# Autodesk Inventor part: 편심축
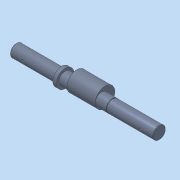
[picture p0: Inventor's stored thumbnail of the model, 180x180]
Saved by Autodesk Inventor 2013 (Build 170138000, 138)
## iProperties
Manager: 한국ATC센터
Company: 한국ATC센터
Created: 2014-10
Part Number: 편심축
Document SubType Name: Modeling
Designer: 한국ATC센터
Density: 7.86 g/cm^3
Material: 강철, 연강
Mass: 1420.77 g
Surface Area: 286.549 cm^2
Volume: 180.76 cm^3
Author: KYOUNG IL JANG
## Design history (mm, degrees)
sketch "스케치1"
  geometry: L1 (-142, 0)-(142, 0); L2 (-142, 0)-(-142, 12.5); L3 (-142, 12.5)-(-52, 12.5); L4 (-52, 12.5)-(-52, 17.5); L5 (-52, 17.5)-(-45, 17.5); L6 (-45, 17.5)-(-45, 12.5); L7 (-45, 12.5)-(48.65, 12.5); L8 (48.65, 12.5)-(48.65, 11.95); L9 (48.65, 11.95)-(50, 11.95); L10 (50, 11.95)-(50, 12.5); L11 (50, 12.5)-(142, 12.5); L12 (142, 12.5)-(142, 0); L13 (109, 12.5)-(109, 9.1); L14 (109, 9.1)-(134, 9.1); L15 (134, 9.1)-(134, 12.5); L16 (117, -12.5)-(119.5, -12.5); L17 (119.5, -12.5)-(117, -10); L18 (117, -10)-(117, -12.5); L19 (-109, 12.5)-(-109, 9.1); L20 (-109, 9.1)-(-134, 9.1); L21 (-134, 9.1)-(-134, 12.5); L22 (-117, -12.5)-(-117, -10); L23 (-117, -10)-(-114.5, -12.5); L24 (-114.5, -12.5)-(-117, -12.5); 2 further points
  constraints: 48 end point, 11 parallel, 8 perpendicular, 5 collinear, 4 point on line, 1 coincident, 1 horizontal, 1 midpoint, 1 vertical
  dimensions: "d0" = 284 distance of L1.start L1.end (derived); "d1" = 25 diameter of L3 L1; "d2" = 35 diameter of L5 L1; "d3" = 90 distance of L2.end L3.end; "d4" = 187 distance between parallel lines of L12 L6; "d6" = 1.35 distance of L8.end L9.end; "d7" = 23.9 diameter of L9 L1; "d8" = 3.4 distance between parallel lines of L14 L11; "d9" = 8 distance between parallel lines of L15 L12; "d10" = 25 distance of L13.end L14.end; "d11" = 25 diameter of L16 L1 (= d1); "d12" = 25 distance from line of L12 L16.start; "d13" = 45 deg angle of L17 L18; "d14" = 5 diameter of L16.end L18; "d27" = 92 distance between parallel lines of L10 L12; "d32" = 7 distance of L4.end L5.end; "d33" = 8 distance between parallel lines of L2 L21; "d34" = 25 distance between parallel lines of L21 L19; "d35" = 3.4 distance between parallel lines of L3 L20; "d36" = 25 distance from line of L22.start L2; "d37" = 5 diameter of L23.end L22
revolve "회전1" stored, may be unused: angle "d15" = 90 deg
revolve "회전2" stored, may be unused: angle "d16" = 90 deg
revolve "회전3" stored, may be unused: angle "d38" = 90 deg
extrude "돌출1" cut sketch "스케치1" stored distance "d17" = 8; taper "d18" = 0 deg
fillet "모깎기1" dims "d19" = 4
node "작업 평면1"
sketch "스케치2"
  geometry: L1 (12.99, -6.5)-(8.66, -14); L2 (-12.99, -6.5)-(-8.66, -14); C1 r 12.5 at (0, 0) reference; C2 r 19.5 at (0, 7); A1 r 15 centre (0, 1) between (12.99, -6.5) and (-12.99, -6.5); A2 r 10 centre (0, -9) between (-8.66, -14) and (8.66, -14); 1 further point
  constraints: 5 tangent, 4 end point, 4 point on circle, 3 centre point, 3 vertical alignment
  dimensions: "d21" = 7 distance of point (0, 0) C2.centre; "d30" = 39 diameter of C2 (derived); "d39" = 10 distance of A2.centre A1.centre; "d40" = 30 diameter of A1; "d41" = 20 diameter of A2; "d42" = 1 distance of point (0, 0) A1.centre
extrude "돌출2" join sketch "스케치2" distance "d22" = 56; taper "d23" = 0 deg
chamfer "모따기1" distance "d24" = 1; stored, may be unused: second distance "d25" = 2, angle "d26" = 45 deg
node "솔리드1"
other parameters: "d20" = 16
